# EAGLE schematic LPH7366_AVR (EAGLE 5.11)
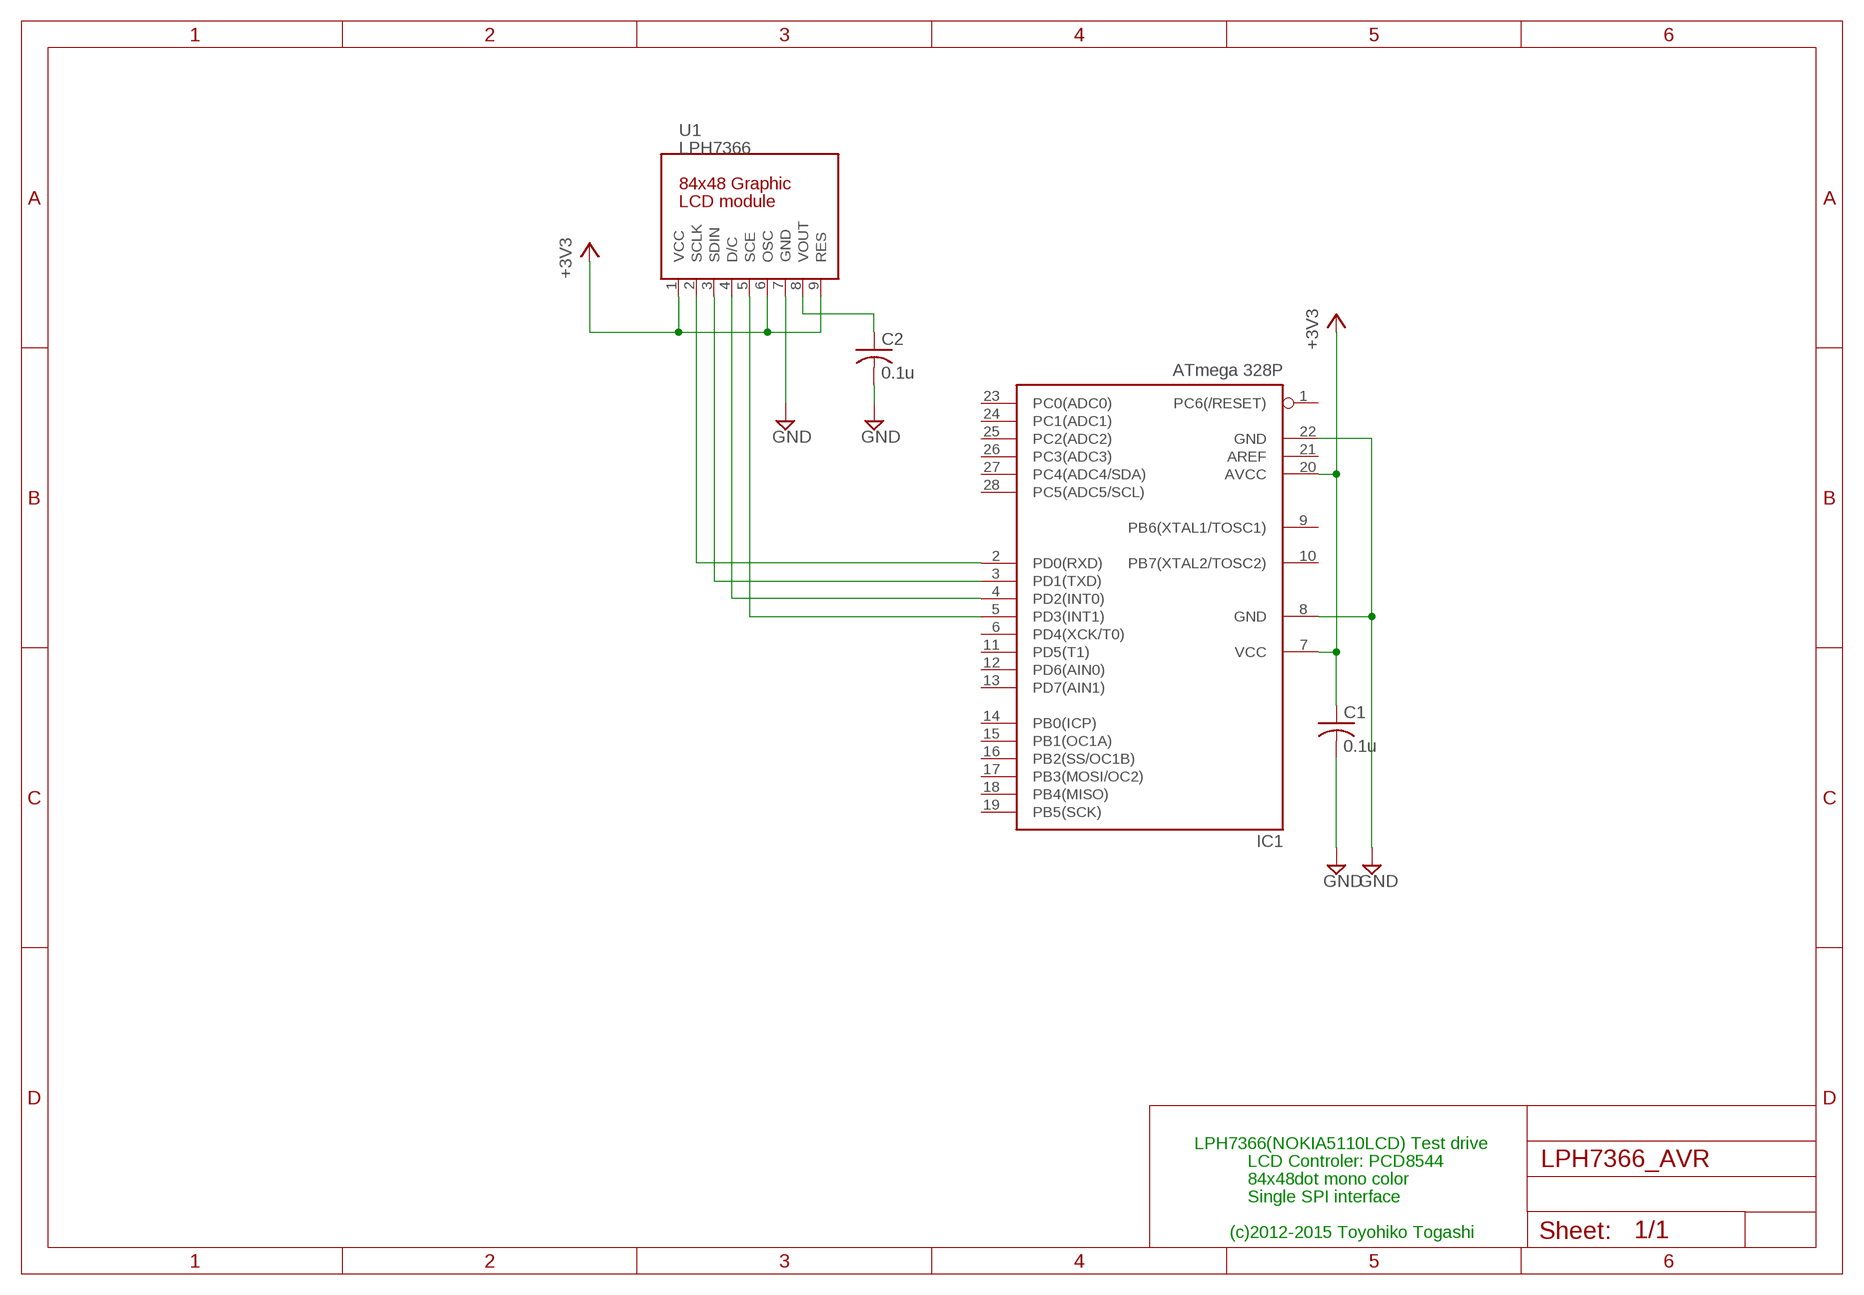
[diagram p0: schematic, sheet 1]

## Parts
C1  0.1u  C-US025-024X044  [C025-024X044]
C2  0.1u  C-US025-024X044  [C025-024X044]
IC1  ATmega 328P  MEGA8-P  [DIL28-3]
U1  LPH7366  [LPH7366]

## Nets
+3V3: C1.1 IC1.7(VCC) IC1.20(AVCC) U1.1(VCC) U1.6(OSC) U1.9(RES)
GND: C1.2 C2.2 IC1.8(GND) IC1.22(GND)
N$1: C2.1 U1.8(VOUT)
N$2: IC1.4(PD2(INT0)) U1.4(D/C)
N$3: IC1.2(PD0(RXD)) U1.2(SCLK)
N$4: IC1.3(PD1(TXD)) U1.3(SDIN)
N$5: IC1.5(PD3(INT1)) U1.5(SCE)
Unconnected: IC1.1(PC6(/RESET)) IC1.6(PD4(XCK/T0)) IC1.9(PB6(XTAL1/TOSC1)) IC1.10(PB7(XTAL2/TOSC2)) IC1.11(PD5(T1)) IC1.12(PD6(AIN0)) IC1.13(PD7(AIN1)) IC1.14(PB0(ICP)) IC1.15(PB1(OC1A)) IC1.16(PB2(SS/OC1B)) IC1.17(PB3(MOSI/OC2)) IC1.18(PB4(MISO)) IC1.19(PB5(SCK)) IC1.21(AREF) IC1.23(PC0(ADC0)) IC1.24(PC1(ADC1)) IC1.25(PC2(ADC2)) IC1.26(PC3(ADC3)) IC1.27(PC4(ADC4/SDA)) IC1.28(PC5(ADC5/SCL))

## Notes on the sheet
- LPH7366(NOKIA5110LCD) Test drive
- LCD Controler: PCD8544
- 84x48dot mono color
- Single SPI interface
- (c)2012-2015 Toyohiko Togashi

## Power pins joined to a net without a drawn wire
GND: U1.7(GND)

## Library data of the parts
C1 C2 = rcl:C-US: CAPACITOR, American symbol
IC1 = atmel:MEGA8-P: MICROCONTROLLER 8 Kbytes FLASH, 1 kbytes SRAM, 512 bytes EEPROM, USART, 4-channel 10 bit ADC, 2-channel 8 bit ADC Pin compatible with Atmega48, ATMega88, ATMega168 Source: avr.lbr
U1 = TOG:LPH7366: Graphic LCD module Monocrome 84x48 dots LCD Controler Philips PCD8544 NOKIA5110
